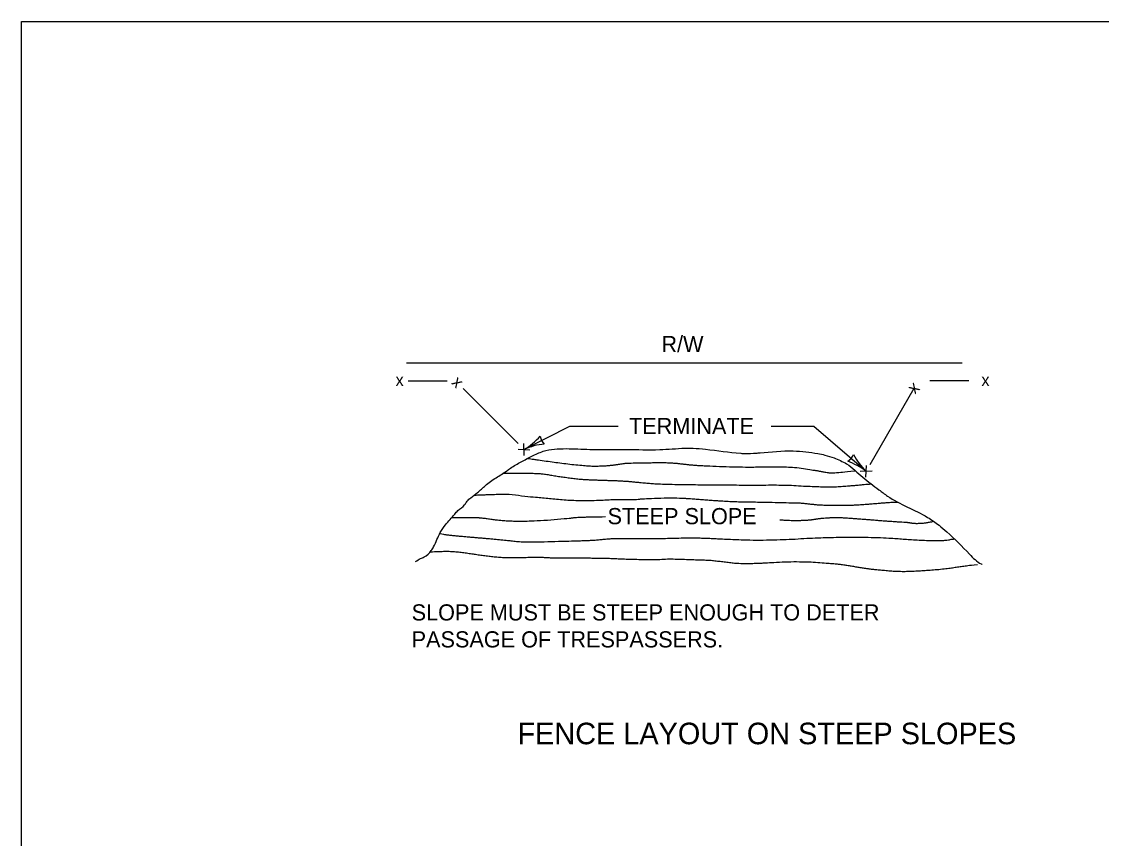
# Model space of a CAD drawing. Extents: x 49991.4 to 50021, y 49987.6 to 50011.4.
# Drawn here: x 49999.384 to 50003.386, y 49995.969 to 49998.999 of the extents above; entities that cross this region are included whole.
import ezdxf

# ---------------------------------------------------------------- set-up
doc = ezdxf.new("R2010")
doc.units = 0
for name, color, linetype in [('Level 1', 7, 'Continuous'), ('Level 2', 7, 'Continuous'), ('Level 3', 7, 'Continuous')]:
    doc.layers.add(name, color=color, linetype=linetype)

msp = doc.modelspace()

# ---------------------------------------------------------------- linework, layer by layer
at = {"layer": 'Level 1'}
for p, q in [((50000.8099, 49997.7329), (50002.8697, 49997.7329)), ((50000.8165, 49997.6664), (50000.9612, 49997.6664)), ((50001.2243, 49997.4337), (50001.0198, 49997.6382)), ((50002.6914, 49997.6382), (50002.5277, 49997.3548)), ((50002.8947, 49997.6664), (50002.75, 49997.6664))]:
    msp.add_line(p, q, dxfattribs=at)
msp.add_lwpolyline([(49999.3835, 49998.9992), (50016.7501, 49998.9992), (50016.7501, 49987.7988), (49999.3835, 49987.7988)], close=True, dxfattribs=at)
for points in [[(50001.2468, 49997.3895), (50001.2449, 49997.4336)], [(50001.2238, 49997.4126), (50001.2679, 49997.4105)], [(50002.5132, 49997.3086), (50002.5151, 49997.3527)], [(50002.5362, 49997.3317), (50002.4921, 49997.3296)]]:
    msp.add_lwpolyline(points, dxfattribs=at)
msp.add_spline([(50000.8441, 49996.9957), (50000.8625, 49997.0074), (50000.876, 49997.0129), (50000.9023, 49997.0364), (50000.911, 49997.0509), (50000.9355, 49997.1034), (50000.9549, 49997.1324), (50000.989, 49997.1722), (50001.0006, 49997.1849), (50001.0259, 49997.2066), (50001.0356, 49997.2202), (50001.0482, 49997.2329), (50001.0735, 49997.2519), (50001.1026, 49997.2782), (50001.1424, 49997.3071), (50001.1821, 49997.3325), (50001.1957, 49997.3424), (50001.2354, 49997.366), (50001.2752, 49997.3868), (50001.3168, 49997.4049), (50001.3584, 49997.413), (50001.4019, 49997.4148), (50001.4898, 49997.4121), (50001.6251, 49997.4121), (50001.7488, 49997.4111), (50001.8426, 49997.4165), (50001.8725, 49997.4165), (50001.9189, 49997.4129), (50002.0493, 49997.3975), (50002.0657, 49997.3966), (50002.1063, 49997.3984), (50002.1208, 49997.3993), (50002.2436, 49997.4065), (50002.2909, 49997.4028), (50002.3353, 49997.3965), (50002.3614, 49997.391), (50002.3951, 49997.3802), (50002.4414, 49997.3584), (50002.502, 49997.3086), (50002.5617, 49997.2624), (50002.5935, 49997.2388), (50002.7419, 49997.16), (50002.7843, 49997.131), (50002.8131, 49997.1066), (50002.8977, 49997.0232), (50002.941, 49996.987), (50002.9449, 49996.9852)], degree=3, dxfattribs=at)
for points in [[(50001.2594, 49997.3788), (50001.2698, 49997.3772), (50001.2802, 49997.3757), (50001.2906, 49997.3741), (50001.3201, 49997.3698), (50001.3497, 49997.3659), (50001.3793, 49997.362), (50001.4089, 49997.3581), (50001.4385, 49997.355), (50001.4683, 49997.3523), (50001.4876, 49997.3506), (50001.5069, 49997.35), (50001.5262, 49997.3505), (50001.5401, 49997.3509), (50001.5539, 49997.3517), (50001.5678, 49997.3532), (50001.5735, 49997.3538), (50001.5791, 49997.3545), (50001.5847, 49997.3553), (50001.5904, 49997.3561), (50001.596, 49997.357), (50001.6016, 49997.3578), (50001.6072, 49997.3586), (50001.6129, 49997.3594), (50001.6185, 49997.3601), (50001.6242, 49997.3607), (50001.6298, 49997.3612), (50001.6355, 49997.3613), (50001.6503, 49997.3617), (50001.6651, 49997.362), (50001.6799, 49997.3622), (50001.7012, 49997.3626), (50001.7224, 49997.3629), (50001.7437, 49997.3631), (50001.763, 49997.3633), (50001.7824, 49997.3626), (50001.8017, 49997.3613), (50001.8077, 49997.3609), (50001.8136, 49997.3604), (50001.8196, 49997.3597), (50001.8255, 49997.3591), (50001.8315, 49997.3584), (50001.8375, 49997.3577), (50001.8434, 49997.357), (50001.8493, 49997.3563), (50001.8553, 49997.3556), (50001.8612, 49997.355), (50001.8672, 49997.3545), (50001.8732, 49997.354), (50001.8889, 49997.3529), (50001.9047, 49997.352), (50001.9205, 49997.3513), (50001.9704, 49997.3491), (50002.0203, 49997.3472), (50002.0703, 49997.3467), (50002.0977, 49997.3465), (50002.125, 49997.3475), (50002.1524, 49997.3476), (50002.1766, 49997.3477), (50002.2007, 49997.3479), (50002.2249, 49997.3467), (50002.2573, 49997.3451), (50002.2894, 49997.34), (50002.3215, 49997.3349), (50002.3268, 49997.3341), (50002.3321, 49997.3332), (50002.3374, 49997.3323), (50002.3427, 49997.3313), (50002.348, 49997.3301), (50002.3533, 49997.3291), (50002.3612, 49997.3276), (50002.3691, 49997.3265), (50002.3772, 49997.3254), (50002.3798, 49997.3251), (50002.3825, 49997.3248), (50002.3852, 49997.3249), (50002.3904, 49997.3251), (50002.3955, 49997.3255), (50002.4007, 49997.3258), (50002.4251, 49997.3275), (50002.4494, 49997.3303), (50002.4737, 49997.3321)], [(50001.1681, 49997.3235), (50001.2046, 49997.3245), (50001.2412, 49997.3242), (50001.2777, 49997.3234), (50001.2935, 49997.3231), (50001.3094, 49997.3219), (50001.3251, 49997.3198), (50001.3445, 49997.3172), (50001.3636, 49997.3135), (50001.383, 49997.3107), (50001.4042, 49997.3077), (50001.4254, 49997.3047), (50001.4467, 49997.3025), (50001.4613, 49997.3011), (50001.4759, 49997.3001), (50001.4906, 49997.2995), (50001.5053, 49997.2989), (50001.5199, 49997.2984), (50001.5346, 49997.2979), (50001.5493, 49997.2974), (50001.564, 49997.297), (50001.5786, 49997.2965), (50001.5933, 49997.296), (50001.6079, 49997.2953), (50001.6226, 49997.2943), (50001.6275, 49997.294), (50001.6324, 49997.2937), (50001.6373, 49997.2932), (50001.652, 49997.2918), (50001.6667, 49997.2903), (50001.6815, 49997.2889), (50001.6913, 49997.288), (50001.7011, 49997.2871), (50001.7109, 49997.2862), (50001.7207, 49997.2853), (50001.7305, 49997.2847), (50001.7404, 49997.2843), (50001.7771, 49997.2829), (50001.8138, 49997.282), (50001.8506, 49997.2816), (50001.9279, 49997.2808), (50002.0052, 49997.2802), (50002.0825, 49997.2797), (50002.1221, 49997.2795), (50002.1617, 49997.2803), (50002.2013, 49997.2797), (50002.2371, 49997.2793), (50002.2728, 49997.2764), (50002.3086, 49997.2751), (50002.333, 49997.2742), (50002.3575, 49997.2733), (50002.382, 49997.2733), (50002.4049, 49997.2734), (50002.4278, 49997.275), (50002.4507, 49997.2769), (50002.4678, 49997.2783), (50002.4848, 49997.2799), (50002.5019, 49997.2814), (50002.5124, 49997.2824), (50002.523, 49997.2833), (50002.5336, 49997.2841)], [(50001.0611, 49997.2426), (50001.0716, 49997.243), (50001.0822, 49997.2434), (50001.0927, 49997.2437), (50001.1101, 49997.2443), (50001.1275, 49997.2449), (50001.1449, 49997.2455), (50001.191, 49997.2471), (50001.2371, 49997.2396), (50001.2831, 49997.2355), (50001.3085, 49997.2332), (50001.3339, 49997.2306), (50001.3594, 49997.2283), (50001.3877, 49997.2258), (50001.416, 49997.2235), (50001.4444, 49997.2228), (50001.4795, 49997.2219), (50001.5146, 49997.2233), (50001.5497, 49997.2246), (50001.562, 49997.2251), (50001.5742, 49997.2261), (50001.5865, 49997.2264), (50001.5923, 49997.2266), (50001.5981, 49997.2267), (50001.6039, 49997.2267), (50001.6097, 49997.2266), (50001.6154, 49997.2265), (50001.6212, 49997.2264), (50001.627, 49997.2264), (50001.6328, 49997.2263), (50001.6386, 49997.2262), (50001.6444, 49997.2261), (50001.6502, 49997.2263), (50001.656, 49997.2264), (50001.6686, 49997.2268), (50001.6811, 49997.2286), (50001.6937, 49997.2291), (50001.7413, 49997.2313), (50001.7891, 49997.2331), (50001.8368, 49997.2309), (50001.8474, 49997.2304), (50001.8581, 49997.2298), (50001.8687, 49997.229), (50001.8793, 49997.2281), (50001.8899, 49997.2273), (50001.9005, 49997.2265), (50001.9112, 49997.2256), (50001.9218, 49997.2248), (50001.9324, 49997.2239), (50001.943, 49997.2231), (50001.9537, 49997.2225), (50001.9643, 49997.2218), (50001.9897, 49997.2203), (50002.0151, 49997.2187), (50002.0406, 49997.2181), (50002.0722, 49997.2174), (50002.1037, 49997.217), (50002.1353, 49997.2163), (50002.1765, 49997.2155), (50002.2178, 49997.2146), (50002.259, 49997.2136), (50002.266, 49997.2135), (50002.273, 49997.2131), (50002.28, 49997.2124), (50002.287, 49997.2117), (50002.294, 49997.211), (50002.301, 49997.2102), (50002.308, 49997.2095), (50002.315, 49997.2087), (50002.322, 49997.208), (50002.329, 49997.2072), (50002.336, 49997.2067), (50002.343, 49997.2063), (50002.3523, 49997.2058), (50002.3617, 49997.2054), (50002.371, 49997.2054), (50002.3762, 49997.2054), (50002.3813, 49997.2054), (50002.3865, 49997.2054), (50002.4061, 49997.2054), (50002.4258, 49997.2054), (50002.4454, 49997.2054), (50002.4628, 49997.2054), (50002.4802, 49997.2061), (50002.4975, 49997.2074), (50002.5149, 49997.2087), (50002.5323, 49997.2102), (50002.5497, 49997.2115), (50002.567, 49997.2129), (50002.5844, 49997.2142), (50002.6017, 49997.2154), (50002.6104, 49997.2161), (50002.6191, 49997.2162), (50002.6277, 49997.2165), (50002.6285, 49997.2165), (50002.6293, 49997.2166), (50002.6301, 49997.2166)], [(50000.9781, 49997.1598), (50000.9869, 49997.1597), (50000.9956, 49997.1596), (50001.0044, 49997.1595), (50001.024, 49997.1593), (50001.0437, 49997.1597), (50001.0633, 49997.1595), (50001.0675, 49997.1595), (50001.0718, 49997.1593), (50001.076, 49997.159), (50001.0803, 49997.1587), (50001.0845, 49997.1584), (50001.0887, 49997.1579), (50001.0972, 49997.157), (50001.1056, 49997.1559), (50001.114, 49997.1548), (50001.1225, 49997.1537), (50001.1309, 49997.1524), (50001.1393, 49997.1513), (50001.1478, 49997.1502), (50001.1562, 49997.1494), (50001.1647, 49997.1486), (50001.1747, 49997.1477), (50001.1847, 49997.1472), (50001.1947, 49997.1468), (50001.2195, 49997.1459), (50001.2443, 49997.1458), (50001.2691, 49997.1468), (50001.3198, 49997.1489), (50001.3704, 49997.1528), (50001.4209, 49997.1576), (50001.426, 49997.1581), (50001.4311, 49997.1591), (50001.4363, 49997.1594), (50001.4455, 49997.1601), (50001.4548, 49997.1605), (50001.4641, 49997.1609), (50001.4733, 49997.1612), (50001.4826, 49997.1616), (50001.4919, 49997.1618), (50001.5104, 49997.1622), (50001.529, 49997.1624), (50001.5475, 49997.1625)], [(50002.1947, 49997.1509), (50002.2041, 49997.1506), (50002.2135, 49997.1497), (50002.2229, 49997.1493), (50002.2359, 49997.1488), (50002.249, 49997.1486), (50002.262, 49997.1486), (50002.2686, 49997.1487), (50002.2751, 49997.1489), (50002.2816, 49997.1491), (50002.2882, 49997.1494), (50002.2947, 49997.1497), (50002.3012, 49997.1502), (50002.3052, 49997.1505), (50002.3093, 49997.1509), (50002.3133, 49997.1515), (50002.3173, 49997.1521), (50002.3213, 49997.1527), (50002.3253, 49997.1533), (50002.3294, 49997.1539), (50002.3334, 49997.1545), (50002.3374, 49997.1551), (50002.3414, 49997.1557), (50002.3454, 49997.1561), (50002.3495, 49997.1565), (50002.3637, 49997.1579), (50002.3779, 49997.1587), (50002.3921, 49997.1592), (50002.4017, 49997.1596), (50002.4114, 49997.1598), (50002.421, 49997.1592), (50002.4374, 49997.1582), (50002.4539, 49997.1571), (50002.4703, 49997.1558), (50002.4867, 49997.1546), (50002.5031, 49997.1533), (50002.5196, 49997.1521), (50002.536, 49997.1508), (50002.5524, 49997.1495), (50002.5688, 49997.1482), (50002.5852, 49997.1469), (50002.6017, 49997.1458), (50002.6181, 49997.1446), (50002.6326, 49997.1436), (50002.6471, 49997.1429), (50002.6616, 49997.1419), (50002.6639, 49997.1418), (50002.6663, 49997.1415), (50002.6686, 49997.1412), (50002.6709, 49997.1409), (50002.6733, 49997.1405), (50002.6756, 49997.1402), (50002.6779, 49997.1398), (50002.6803, 49997.1395), (50002.6826, 49997.1391), (50002.6849, 49997.1388), (50002.6872, 49997.1385), (50002.6896, 49997.1383), (50002.6958, 49997.1378), (50002.702, 49997.1377), (50002.7083, 49997.1378), (50002.7145, 49997.1379), (50002.7207, 49997.1382), (50002.727, 49997.1389), (50002.7333, 49997.1395), (50002.7395, 49997.1403), (50002.7457, 49997.1415), (50002.752, 49997.1427), (50002.7582, 49997.1439), (50002.7644, 49997.1455)], [(50000.9335, 49997.0997), (50000.945, 49997.0974), (50000.9566, 49997.0956), (50000.9683, 49997.0943), (50000.9849, 49997.0926), (50001.0016, 49997.091), (50001.0183, 49997.0896), (50001.0349, 49997.0881), (50001.0516, 49997.0867), (50001.0683, 49997.0852), (50001.0849, 49997.0838), (50001.1016, 49997.0824), (50001.1182, 49997.0809), (50001.1349, 49997.0795), (50001.1515, 49997.0778), (50001.1682, 49997.0762), (50001.1795, 49997.0751), (50001.1907, 49997.0738), (50001.202, 49997.0726), (50001.2238, 49997.0704), (50001.2458, 49997.0687), (50001.2677, 49997.0689), (50001.3209, 49997.0695), (50001.374, 49997.071), (50001.4272, 49997.0725), (50001.4462, 49997.0731), (50001.4652, 49997.0736), (50001.4842, 49997.0743), (50001.4927, 49997.0747), (50001.5013, 49997.0752), (50001.5098, 49997.0759), (50001.5184, 49997.0766), (50001.5269, 49997.0775), (50001.5354, 49997.0782), (50001.544, 49997.079), (50001.5525, 49997.0797), (50001.561, 49997.0804), (50001.5696, 49997.0811), (50001.5781, 49997.0815), (50001.5867, 49997.0815), (50001.6282, 49997.0818), (50001.6698, 49997.0814), (50001.7113, 49997.0815), (50001.7783, 49997.0818), (50001.8454, 49997.0844), (50001.9124, 49997.0832), (50001.9304, 49997.0829), (50001.9485, 49997.0813), (50001.9665, 49997.0805), (50001.9967, 49997.0792), (50002.027, 49997.0779), (50002.0573, 49997.0769), (50002.1075, 49997.0754), (50002.1578, 49997.0761), (50002.208, 49997.0777), (50002.2509, 49997.0792), (50002.2937, 49997.0826), (50002.3366, 49997.084), (50002.3746, 49997.0853), (50002.4126, 49997.0863), (50002.4506, 49997.0867), (50002.4551, 49997.0868), (50002.4597, 49997.0868), (50002.4642, 49997.0867), (50002.5099, 49997.0863), (50002.5557, 49997.0853), (50002.6014, 49997.0831), (50002.6262, 49997.0819), (50002.6509, 49997.0792), (50002.6757, 49997.0776), (50002.7034, 49997.0759), (50002.7311, 49997.0749), (50002.7588, 49997.074), (50002.7778, 49997.0735), (50002.7969, 49997.0742), (50002.8159, 49997.0758), (50002.8228, 49997.0764), (50002.8293, 49997.0789), (50002.8362, 49997.0794), (50002.8378, 49997.0796), (50002.8394, 49997.0797), (50002.8411, 49997.0797)], [(50000.8988, 49997.0319), (50000.9115, 49997.0329), (50000.9243, 49997.0334), (50000.937, 49997.0337), (50000.9576, 49997.0343), (50000.9783, 49997.0339), (50000.9989, 49997.0319), (50001.0086, 49997.031), (50001.0183, 49997.0299), (50001.0279, 49997.0285), (50001.0376, 49997.0271), (50001.0472, 49997.0257), (50001.0569, 49997.0243), (50001.0665, 49997.0229), (50001.0762, 49997.0215), (50001.0858, 49997.0201), (50001.0954, 49997.0187), (50001.1051, 49997.0176), (50001.1148, 49997.0164), (50001.1353, 49997.014), (50001.1559, 49997.012), (50001.1766, 49997.011), (50001.1877, 49997.0105), (50001.1988, 49997.0104), (50001.2099, 49997.0106), (50001.221, 49997.0108), (50001.2321, 49997.011), (50001.2432, 49997.0112), (50001.2544, 49997.0115), (50001.2655, 49997.0118), (50001.2766, 49997.012), (50001.2877, 49997.0122), (50001.2988, 49997.0121), (50001.3099, 49997.0118), (50001.3244, 49997.0115), (50001.3389, 49997.0103), (50001.3534, 49997.01), (50001.3703, 49997.0097), (50001.3872, 49997.0094), (50001.4041, 49997.0094), (50001.421, 49997.0093), (50001.4379, 49997.0093), (50001.4548, 49997.0093), (50001.4718, 49997.0092), (50001.4887, 49997.0092), (50001.5056, 49997.0091), (50001.5225, 49997.009), (50001.5394, 49997.0087), (50001.5563, 49997.0082), (50001.5785, 49997.0076), (50001.6007, 49997.0062), (50001.623, 49997.0054), (50001.6555, 49997.0044), (50001.6881, 49997.0038), (50001.7206, 49997.0036), (50001.7493, 49997.0034), (50001.7779, 49997.0063), (50001.8066, 49997.0054), (50001.8343, 49997.0046), (50001.862, 49997.0035), (50001.8897, 49997.0026), (50001.8997, 49997.0023), (50001.9097, 49997.0021), (50001.9197, 49997.0017), (50001.9295, 49997.0014), (50001.9392, 49997.0007), (50001.9489, 49996.9996), (50001.9587, 49996.9985), (50001.9684, 49996.9974), (50001.9781, 49996.9962), (50001.9878, 49996.995), (50001.9975, 49996.9937), (50002.0072, 49996.9925), (50002.017, 49996.9913), (50002.0267, 49996.9905), (50002.0365, 49996.9899), (50002.0491, 49996.9891), (50002.0616, 49996.9889), (50002.0742, 49996.989), (50002.0945, 49996.9893), (50002.1148, 49996.9898), (50002.1351, 49996.9908), (50002.1399, 49996.9911), (50002.1448, 49996.9915), (50002.1496, 49996.9917), (50002.1924, 49996.994), (50002.2353, 49996.9959), (50002.2781, 49996.9953), (50002.3103, 49996.9949), (50002.3426, 49996.9924), (50002.3748, 49996.9898), (50002.3909, 49996.9885), (50002.407, 49996.9873), (50002.423, 49996.9853), (50002.4311, 49996.9843), (50002.4392, 49996.9832), (50002.4472, 49996.9818), (50002.4552, 49996.9805), (50002.4633, 49996.9791), (50002.4713, 49996.9777), (50002.4793, 49996.9763), (50002.4874, 49996.9749), (50002.4954, 49996.9735), (50002.5034, 49996.9721), (50002.5115, 49996.971), (50002.5196, 49996.9699), (50002.537, 49996.9677), (50002.5544, 49996.966), (50002.5718, 49996.9644), (50002.5933, 49996.9624), (50002.6149, 49996.9608), (50002.6365, 49996.9599), (50002.6474, 49996.9595), (50002.6584, 49996.9596), (50002.6693, 49996.9599), (50002.6922, 49996.9607), (50002.7151, 49996.9619), (50002.738, 49996.9635), (50002.7641, 49996.9654), (50002.7903, 49996.9675), (50002.8163, 49996.9707), (50002.8347, 49996.973), (50002.853, 49996.9765), (50002.8714, 49996.9788), (50002.8897, 49996.9812), (50002.9081, 49996.9834), (50002.9265, 49996.9852)]]:
    msp.add_open_spline(points, degree=3, dxfattribs=at)
at = {"layer": 'Level 3'}
for p, q in [((50001.2458, 49997.4116), (50001.4154, 49997.4988)), ((50001.4154, 49997.4988), (50001.5952, 49997.4988)), ((50002.162, 49997.4988), (50002.3208, 49997.4988)), ((50002.3208, 49997.4988), (50002.5142, 49997.3307))]:
    msp.add_line(p, q, dxfattribs=at)
for centre, radius, start, end in [((50001.1291, 49997.6132), 0.233, 300.0534, 319.3033), ((50001.3393, 49997.2099), 0.2223, 94.6821, 114.8656), ((50001.3598, 49997.4702), 0.0548, 189.3649, 225.0873), ((50002.4174, 49997.4148), 0.0548, 301.1281, 336.8504), ((50002.6668, 49997.4923), 0.2223, 206.4452, 226.6288), ((50002.3701, 49997.1475), 0.233, 51.8166, 71.0664)]:
    msp.add_arc(centre, radius, start, end, dxfattribs=at)

# ---------------------------------------------------------------- texts
at = {"layer": 'Level 1'}
for p in [(50000.7698, 49997.6472), (50002.9414, 49997.6472)]:
    msp.add_text('x', height=0.0451, dxfattribs=at).set_placement(p)
for rotation, p in [(135, (50001.0198, 49997.6608)), (225, (50002.6914, 49997.6608))]:
    msp.add_text('x', height=0.0451, rotation=rotation, dxfattribs=at).set_placement(p)
at = {"layer": 'Level 2'}
for s, height, p in [('R/W', 0.06, (50001.7553, 49997.7729)), ('TERMINATE', 0.06, (50001.6352, 49997.4688)), ('STEEP SLOPE', 0.06, (50001.5556, 49997.1345)), ('SLOPE MUST BE STEEP ENOUGH TO DETER', 0.06, (50000.8294, 49996.7773)), ('PASSAGE OF TRESPASSERS.', 0.06, (50000.8294, 49996.6773)), ('FENCE LAYOUT ON STEEP SLOPES', 0.08, (50001.2217, 49996.3182))]:
    msp.add_text(s, height=height, dxfattribs=at).set_placement(p)

doc.saveas('drawing.dxf')
